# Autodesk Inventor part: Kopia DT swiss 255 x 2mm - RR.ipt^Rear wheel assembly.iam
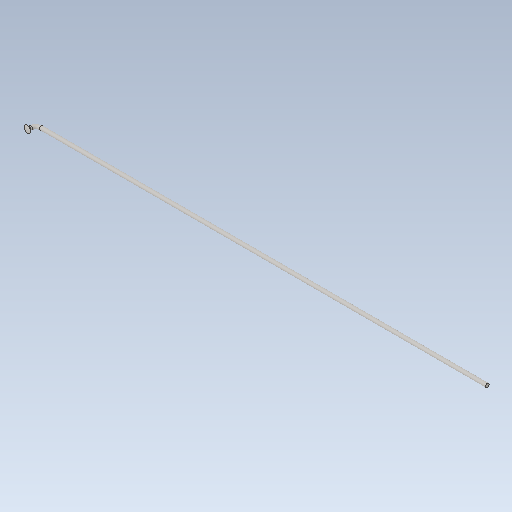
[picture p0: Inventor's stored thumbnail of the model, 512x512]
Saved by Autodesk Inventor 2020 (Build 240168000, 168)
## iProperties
Created: 2017-09
Part Number: Kopia DT swiss 255 x 2mm - RR.ipt^Rear wheel assembly.iam
Material: Ogólny
Document SubType Name: Modeling
Designer: Tomasz
Density: 1 g/cm^3
Appearance: Domyślna
Sending System: SolidWorks 2017
Last Author: Tomasz
Last Saved: 2017-09-11
Author: Tomasz
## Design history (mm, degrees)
feature "DT swiss 255 x 2mm - RR.ipt"
node "Bryła1"
